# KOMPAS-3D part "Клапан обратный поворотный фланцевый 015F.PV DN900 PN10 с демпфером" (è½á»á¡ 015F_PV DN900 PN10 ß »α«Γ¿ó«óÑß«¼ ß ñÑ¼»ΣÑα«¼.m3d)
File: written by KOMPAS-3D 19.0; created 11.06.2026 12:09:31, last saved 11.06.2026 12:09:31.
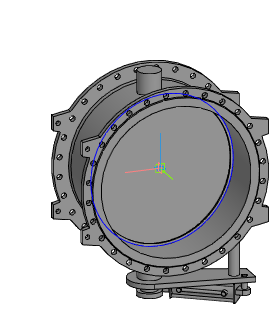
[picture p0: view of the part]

Document properties: Автор: Энергия; Полное имя файла: Z:\3.Личные\kachalov\001_3d для проектировщиков\5.5 Тип 015F.PV Клапан обратный поворотный с двумя эксцентриками\_stp_Клапан 015F.PV DN300-DN1200 с противовесом с демпфером\Клапан 015F_PV DN900 PN10 с противовесом с демпфером.m3d

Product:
- Part/product: Клапан обратный поворотный фланцевый 015F.PV DN900 PN10 с демпфером

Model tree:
1. Операция без истории:1
2. Сплайн:1
     Координата Y = 30; Координата Z = 450; Вес = 1; Координата X = 900; Координата Y = 148.487; Координата Z = 450; Вес = 0.333333; Координата X = 900; Координата Y = 148.487; Координата Z = -450; Вес = 0.333333; Координата Y = 30; Координата Z = -450; Вес = 1; Координата X = -900; Координата Y = -88.4872; Координата Z = -450; Вес = 0.333333; Координата X = -900; Координата Y = -88.4872; Координата Z = 450; Вес = 0.333333; Порядок = 4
